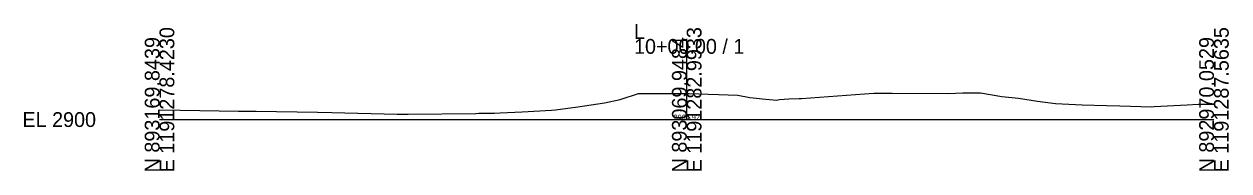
# Model space of a CAD drawing. Extents: x -26 to 203, y -10 to 7027.
# Drawn here: x -25.7 to 202.8, y -9.7 to 18 of the extents above; entities that cross this region are included whole.
import ezdxf

# ---------------------------------------------------------------- set-up
doc = ezdxf.new("R2010")
doc.units = 0
for name, color, linetype in [('Default', 7, 'Continuous'), ('Exist Cross Section Cell', 7, 'Continuous'), ('Prop CMT Pvmt Course 3 Wedge', 7, 'Continuous'), ('Scratch_Level_6', 7, 'Continuous')]:
    doc.layers.add(name, color=color, linetype=linetype)

msp = doc.modelspace()

# ---------------------------------------------------------------- linework, layer by layer
at = {"layer": 'Exist Cross Section Cell'}
for p, q in [((100, 0), (100, 15.24)), ((0, 0), (100, 0)), ((100, 0), (200, 0))]:
    msp.add_line(p, q, dxfattribs=at)
at = {"layer": 'Prop CMT Pvmt Course 3 Wedge'}
for p, q in [((87.36, 3.79), (90.82, 4.91)), ((90.82, 4.91), (98.11, 4.92)), ((98.11, 4.92), (100, 4.92)), ((100, 4.92), (100.47, 4.92)), ((100.47, 4.92), (109.66, 4.64)), ((109.66, 4.64), (111.97, 4.16)), ((121.75, 3.99), (133.7, 4.89)), ((133.7, 4.89), (135.46, 4.97)), ((135.46, 4.97), (135.82, 4.97)), ((135.82, 4.97), (138.96, 4.97)), ((138.96, 4.97), (149.6, 4.96)), ((149.6, 4.96), (152.39, 5.06)), ((152.39, 5.06), (155.75, 5.08)), ((155.75, 5.08), (159.79, 4.35)), ((75.08, 1.82), (79.37, 2.4)), ((79.37, 2.4), (84.42, 3.18)), ((84.42, 3.18), (87.36, 3.79)), ((111.97, 4.16), (115.01, 3.88)), ((115.01, 3.88), (117.12, 3.69)), ((117.12, 3.69), (117.58, 3.77)), ((117.58, 3.77), (119.36, 3.91)), ((119.36, 3.91), (121.3, 3.97)), ((121.3, 3.97), (121.75, 3.99)), ((159.79, 4.35), (162.9, 4.05)), ((162.9, 4.05), (166.56, 3.45)), ((166.56, 3.45), (169.93, 3.02)), ((169.93, 3.02), (175.01, 2.79)), ((175.01, 2.79), (179.64, 2.68)), ((179.64, 2.68), (182.15, 2.59)), ((182.15, 2.59), (188.16, 2.42)), ((188.16, 2.42), (188.65, 2.45)), ((188.65, 2.45), (194.92, 2.78)), ((194.92, 2.78), (197.04, 2.9)), ((197.04, 2.9), (199.02, 2.92)), ((199.02, 2.92), (200, 2.93)), ((0, 1.84), (3.99, 1.78)), ((3.99, 1.78), (14.95, 1.58)), ((14.95, 1.58), (18.35, 1.58)), ((18.35, 1.58), (29.97, 1.39)), ((29.97, 1.39), (32.71, 1.34)), ((32.71, 1.34), (45.05, 0.99)), ((45.05, 0.99), (47.13, 1)), ((47.13, 1), (60, 1.14)), ((60, 1.14), (60.59, 1.18)), ((60.59, 1.18), (63.52, 1.22)), ((63.52, 1.22), (64.63, 1.26)), ((64.63, 1.26), (68.79, 1.44)), ((68.79, 1.44), (74.36, 1.76)), ((74.36, 1.76), (75.08, 1.82))]:
    msp.add_line(p, q, dxfattribs=at)

# ---------------------------------------------------------------- texts
at = {"layer": 'Default'}
msp.add_text('-', height=0.0001, dxfattribs=at).set_placement((0, 0))
at = {"layer": 'Exist Cross Section Cell'}
for s, p in [('E 1191278.4230', (2.8, -10)), ('E 1191282.9933', (102.8, -10)), ('E 1191287.5635', (202.8, -10)), ('N 893169.8439', (0, -10)), ('N 893069.9484', (100, -10)), ('N 892970.0529', (200, -10))]:
    msp.add_text(s, height=2.8, rotation=90, dxfattribs=at).set_placement(p)
for s, p in [('L', (90, 15.24)), ('10+00.00 / 1', (90, 12.44)), ('EL 2900', (-26, -1.4))]:
    msp.add_text(s, height=2.8, dxfattribs=at).set_placement(p)
at = {"layer": 'Scratch_Level_6'}
msp.add_text('2904.92', height=1, dxfattribs=at).set_placement((97.51, -0.08))

doc.saveas('drawing.dxf')
